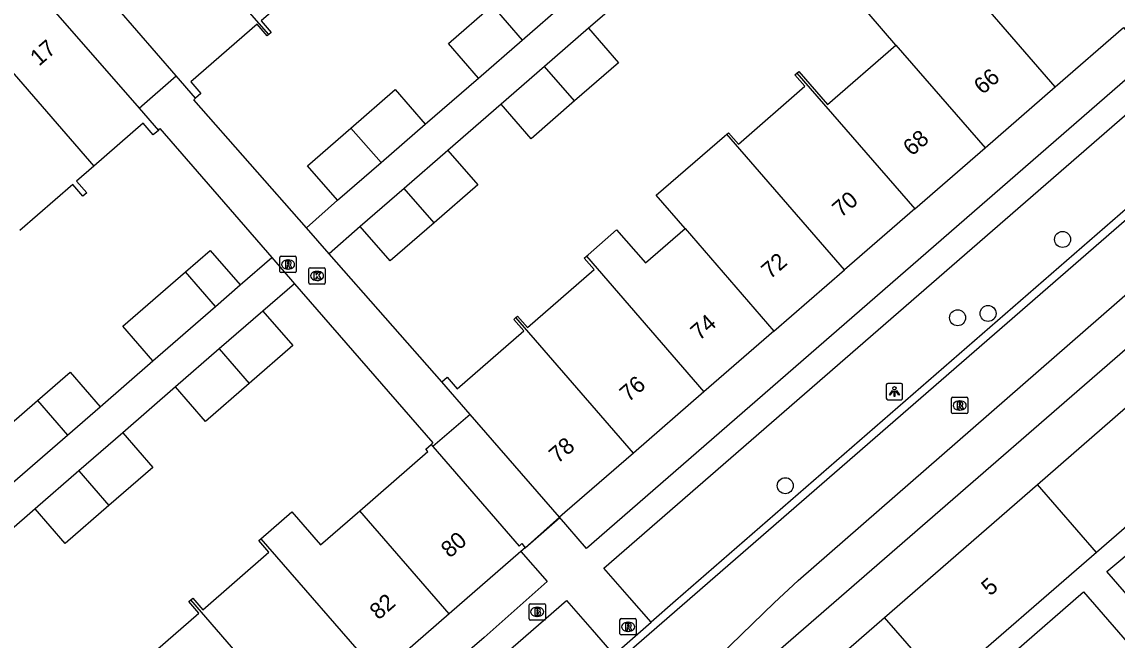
# Model space of a CAD drawing. Extents: x 155888 to 156864, y 383882 to 384671.
# Drawn here: x 156546.3 to 156613.4, y 384111.8 to 384149.6 of the extents above; entities that cross this region are included whole.
import ezdxf

# ---------------------------------------------------------------- set-up
doc = ezdxf.new("R2010")
doc.units = 0
for name, color, linetype in [('IMGEO_Boom', 7, 'Continuous'), ('IMGEO_Brandkraan', 7, 'Continuous'), ('IMGEO_Kolk', 7, 'Continuous'), ('IMGEO_Lichtpunt', 7, 'Continuous'), ('IMGEO_Pand', 7, 'Continuous'), ('IMGEO_Pand_nummerreeks', 7, 'Continuous'), ('IMGEO_Pand_overbouw', 7, 'Continuous'), ('IMGEO_Rijbaan_lokaal_gesloten', 7, 'Continuous'), ('IMGEO_Rijbaan_lokaal_open', 7, 'Continuous'), ('IMGEO_Rioolput', 7, 'Continuous'), ('IMGEO_Voetpad_open', 7, 'Continuous')]:
    doc.layers.add(name, color=color, linetype=linetype)

msp = doc.modelspace()

# ---------------------------------------------------------------- linework, layer by layer
at = {"layer": 'IMGEO_Boom'}
for centre in [(156610.032, 384136.289), (156605.468, 384131.757), (156603.606, 384131.497), (156593.057, 384121.22)]:
    msp.add_circle(centre, 0.489, dxfattribs=at)
at = {"layer": 'IMGEO_Brandkraan'}
for p, q in [((156577.369, 384113.075), (156577.369, 384113.927)), ((156577.444, 384114.001), (156578.296, 384114.001)), ((156577.857, 384113.781), (156577.882, 384113.781)), ((156578.37, 384113.927), (156578.37, 384113.075)), ((156578.296, 384113.001), (156577.444, 384113.001)), ((156577.88, 384113.221), (156577.855, 384113.221))]:
    msp.add_line(p, q, dxfattribs=at)
for points in [[(156577.369, 384113.075), (156577.369, 384113.927)], [(156577.444, 384114.001), (156578.296, 384114.001)], [(156577.717, 384113.701), (156577.717, 384113.301), (156577.93, 384113.301)], [(156577.948, 384113.701), (156577.717, 384113.701)], [(156577.896, 384113.62), (156577.842, 384113.62), (156577.842, 384113.544)], [(156577.842, 384113.544), (156577.895, 384113.544)], [(156577.904, 384113.468), (156577.842, 384113.468), (156577.842, 384113.387)], [(156578.37, 384113.927), (156578.37, 384113.075)], [(156578.296, 384113.001), (156577.444, 384113.001)], [(156577.842, 384113.387), (156577.904, 384113.387)]]:
    msp.add_lwpolyline(points, dxfattribs=at)
for centre, radius, start, end in [((156577.446, 384113.925), 0.0765, 91.55205, 178.44795), ((156577.446, 384113.925), 0.0765, 91.55205, 178.44795), ((156577.897, 384113.582), 0.0379, 267.82845, 90.93552), ((156577.905, 384113.427), 0.0404, 269.87594, 90.50774), ((156577.952, 384113.556), 0.145, 59.4692, 91.53667), ((156577.977, 384113.603), 0.0922, 285.51372, 58.15012), ((156577.982, 384113.411), 0.105, 301.31148, 78.98903), ((156578.294, 384113.925), 0.0765, 1.55205, 88.44795), ((156578.294, 384113.925), 0.0765, 1.55205, 88.44795), ((156577.446, 384113.077), 0.0765, 181.55205, 268.44795), ((156577.446, 384113.077), 0.0765, 181.55205, 268.44795), ((156577.936, 384113.552), 0.251, 268.66757, 293.53466), ((156578.294, 384113.077), 0.0765, 271.55205, 358.44795), ((156578.294, 384113.077), 0.0765, 271.55205, 358.44795)]:
    msp.add_arc(centre, radius, start, end, dxfattribs=at)
for centre, major_axis, ratio, start_param, end_param in [((156577.856, 384113.501), (-0.387, 0.002), 0.722429, 4.712389, 7.853982), ((156577.881, 384113.501), (-0.39, 0.002), 0.717154, 1.570796, 4.712389)]:
    msp.add_ellipse(centre, major_axis=major_axis, ratio=ratio, start_param=start_param, end_param=end_param, dxfattribs=at)
at = {"layer": 'IMGEO_Kolk'}
for p, q in [((156563.894, 384133.628), (156563.894, 384134.48)), ((156563.969, 384134.554), (156564.821, 384134.554)), ((156564.382, 384134.334), (156564.407, 384134.334)), ((156564.895, 384134.48), (156564.895, 384133.628)), ((156564.821, 384133.554), (156563.969, 384133.554)), ((156564.405, 384133.774), (156564.38, 384133.774))]:
    msp.add_line(p, q, dxfattribs=at)
for points in [[(156563.894, 384133.628), (156563.894, 384134.48)], [(156563.969, 384134.554), (156564.821, 384134.554)], [(156564.215, 384134.254), (156564.338, 384134.254), (156564.338, 384134.103), (156564.468, 384134.254), (156564.632, 384134.254), (156564.486, 384134.103), (156564.639, 384133.854), (156564.487, 384133.854), (156564.402, 384134.018), (156564.338, 384133.951), (156564.338, 384133.854), (156564.215, 384133.854), (156564.215, 384134.254)], [(156564.895, 384134.48), (156564.895, 384133.628)], [(156564.821, 384133.554), (156563.969, 384133.554)]]:
    msp.add_lwpolyline(points, dxfattribs=at)
for centre, start, end in [((156563.971, 384134.478), 91.55205, 178.44795), ((156563.971, 384134.478), 91.55205, 178.44795), ((156564.819, 384134.478), 1.55205, 88.44795), ((156564.819, 384134.478), 1.55205, 88.44795), ((156563.971, 384133.63), 181.55205, 268.44795), ((156563.971, 384133.63), 181.55205, 268.44795), ((156564.819, 384133.63), 271.55205, 358.44795), ((156564.819, 384133.63), 271.55205, 358.44795)]:
    msp.add_arc(centre, 0.0765, start, end, dxfattribs=at)
for centre, major_axis, ratio, start_param, end_param in [((156564.381, 384134.054), (-0.387, 0.002), 0.722429, 4.712389, 7.853982), ((156564.406, 384134.054), (-0.39, 0.002), 0.717154, 1.570796, 4.712389)]:
    msp.add_ellipse(centre, major_axis=major_axis, ratio=ratio, start_param=start_param, end_param=end_param, dxfattribs=at)
at = {"layer": 'IMGEO_Lichtpunt'}
for p, q in [((156599.24, 384127.384), (156599.24, 384126.577)), ((156599.24, 384127.384), (156599.24, 384126.577)), ((156600.142, 384127.479), (156599.334, 384127.479)), ((156600.142, 384127.479), (156599.334, 384127.479)), ((156600.236, 384126.577), (156600.236, 384127.384)), ((156600.236, 384126.577), (156600.236, 384127.384)), ((156599.334, 384126.483), (156600.142, 384126.483)), ((156599.334, 384126.483), (156600.142, 384126.483))]:
    msp.add_line(p, q, dxfattribs=at)
for points in [[(156599.614, 384127.048), (156599.653, 384127.02), (156599.465, 384126.758), (156599.427, 384126.785), (156599.614, 384127.048)], [(156599.716, 384127), (156599.763, 384127), (156599.763, 384126.678), (156599.716, 384126.678), (156599.716, 384127)], [(156599.826, 384127.02), (156599.864, 384127.047), (156600.051, 384126.785), (156600.012, 384126.757), (156599.826, 384127.02)]]:
    msp.add_lwpolyline(points, dxfattribs=at)
msp.add_circle((156599.739, 384127.182), 0.0994, dxfattribs=at)
for centre, start, end in [((156599.334, 384127.384), 90, 180), ((156599.334, 384127.384), 90, 180), ((156600.142, 384127.384), 0, 90), ((156600.142, 384127.384), 0, 90), ((156599.334, 384126.577), 180, 270), ((156599.334, 384126.577), 180, 270), ((156600.142, 384126.577), 270, 0), ((156600.142, 384126.577), 270, 360)]:
    msp.add_arc(centre, 0.0946, start, end, dxfattribs=at)
at = {"layer": 'IMGEO_Pand'}
for points in [[(156561.441, 384148.826), (156554.174, 384157.103)], [(156599.829, 384148.182), (156598.187, 384150.072), (156596.034, 384152.551), (156600.336, 384156.287), (156602.489, 384153.808)], [(156609.582, 384145.625), (156604.264, 384151.76), (156604.127, 384151.918), (156602.489, 384153.808)], [(156556.961, 384144.933), (156555.775, 384146.301), (156549.746, 384153.257)], [(156565.766, 384152.585), (156565.653, 384152.487), (156565.036, 384153.196), (156560.967, 384149.66), (156561.583, 384148.95), (156561.441, 384148.826)], [(156547.618, 384151.401), (156547.827, 384151.16), (156547.661, 384151.015), (156553.498, 384144.317), (156554.683, 384142.957)], [(156574.273, 384146.161), (156572.441, 384148.273), (156575.112, 384150.59)], [(156575.112, 384150.59), (156576.951, 384148.484)], [(156576.951, 384148.484), (156579.629, 384150.807)], [(156561.441, 384148.826), (156561.349, 384148.746), (156560.732, 384149.455), (156556.663, 384145.919), (156557.279, 384145.209), (156556.961, 384144.933)], [(156581.015, 384149.21), (156578.326, 384146.876)], [(156581.015, 384149.21), (156582.848, 384147.098), (156580.157, 384144.763)], [(156609.582, 384145.625), (156613.768, 384149.257), (156615.216, 384147.588), (156615.406, 384147.37)], [(156544.113, 384148.367), (156550.722, 384140.76)], [(156574.273, 384146.161), (156576.951, 384148.484)], [(156593.768, 384146.462), (156593.879, 384146.559), (156595.637, 384144.538), (156599.829, 384148.182)], [(156599.829, 384148.182), (156605.287, 384141.898)], [(156578.326, 384146.876), (156575.66, 384144.563)], [(156580.157, 384144.763), (156578.326, 384146.876)], [(156589.471, 384142.727), (156589.576, 384142.818), (156590.187, 384142.118), (156594.254, 384145.654), (156593.645, 384146.356), (156593.768, 384146.462)], [(156593.768, 384146.462), (156600.977, 384138.159)], [(156605.287, 384141.898), (156609.582, 384145.625)], [(156566.47, 384143.098), (156569.183, 384145.452), (156571.018, 384143.337)], [(156580.157, 384144.763), (156577.493, 384142.451), (156575.66, 384144.563)], [(156554.683, 384142.957), (156554.366, 384142.681), (156553.749, 384143.391), (156550.722, 384140.76)], [(156565.654, 384138.684), (156563.819, 384140.799), (156566.47, 384143.098)], [(156566.47, 384143.098), (156568.317, 384140.994)], [(156568.317, 384140.994), (156571.018, 384143.337)], [(156586.92, 384136.96), (156585.16, 384138.991), (156589.341, 384142.614), (156589.471, 384142.727)], [(156596.673, 384134.424), (156589.471, 384142.727)], [(156572.405, 384141.737), (156569.725, 384139.411)], [(156572.405, 384141.737), (156574.24, 384139.622), (156571.558, 384137.295)], [(156600.977, 384138.159), (156605.287, 384141.898)], [(156565.654, 384138.684), (156568.317, 384140.994)], [(156550.722, 384140.76), (156549.679, 384139.853), (156550.296, 384139.143), (156550.061, 384138.938), (156549.444, 384139.648), (156546.193, 384136.824)], [(156569.725, 384139.411), (156567.043, 384137.084)], [(156571.558, 384137.295), (156569.725, 384139.411)], [(156600.977, 384138.159), (156596.673, 384134.424)], [(156571.558, 384137.295), (156568.878, 384134.969), (156567.043, 384137.084)], [(156580.881, 384135.259), (156580.98, 384135.345), (156582.732, 384136.869), (156584.491, 384134.848), (156586.92, 384136.96)], [(156586.92, 384136.96), (156592.361, 384130.682)], [(156556.337, 384134.297), (156557.857, 384135.617), (156559.69, 384133.506)], [(156576.571, 384131.512), (156576.67, 384131.598), (156577.28, 384130.897), (156581.355, 384134.439), (156580.745, 384135.141), (156580.881, 384135.259)], [(156580.881, 384135.259), (156588.075, 384126.964)], [(156554.338, 384128.859), (156552.505, 384130.97), (156556.337, 384134.297)], [(156558.171, 384132.187), (156556.337, 384134.297)], [(156592.361, 384130.682), (156596.673, 384134.424)], [(156558.171, 384132.187), (156559.69, 384133.506)], [(156554.338, 384128.859), (156558.171, 384132.187)], [(156561.079, 384131.906), (156558.407, 384129.585)], [(156561.079, 384131.906), (156562.912, 384129.795), (156560.24, 384127.475)], [(156572.041, 384127.575), (156572.359, 384127.851), (156572.969, 384127.15), (156577.044, 384130.692), (156576.434, 384131.394), (156576.571, 384131.512)], [(156583.759, 384123.219), (156576.571, 384131.512)], [(156592.361, 384130.682), (156588.075, 384126.964)], [(156558.407, 384129.585), (156555.727, 384127.258)], [(156558.407, 384129.585), (156560.24, 384127.475)], [(156608.489, 384121.292), (156617.846, 384129.421)], [(156547.274, 384126.431), (156549.273, 384128.167), (156551.108, 384126.054)], [(156579.234, 384119.292), (156573.771, 384125.581), (156572.041, 384127.575)], [(156560.24, 384127.475), (156557.56, 384125.147), (156555.727, 384127.258)], [(156588.075, 384126.964), (156583.759, 384123.219)], [(156545.749, 384121.4), (156543.914, 384123.513), (156547.274, 384126.431)], [(156547.274, 384126.431), (156549.109, 384124.318)], [(156549.109, 384124.318), (156551.108, 384126.054)], [(156621.464, 384125.256), (156612.102, 384117.132)], [(156545.749, 384121.4), (156549.109, 384124.318)], [(156552.497, 384124.453), (156549.818, 384122.126)], [(156552.497, 384124.453), (156554.332, 384122.34), (156551.651, 384120.012)], [(156567.005, 384119.687), (156571.185, 384123.318), (156571.048, 384123.457), (156571.374, 384123.74)], [(156571.374, 384123.74), (156571.489, 384123.608), (156576.761, 384117.53), (156576.924, 384117.676), (156577.132, 384117.425)], [(156583.759, 384123.219), (156579.569, 384119.583), (156579.234, 384119.292)], [(156549.818, 384122.126), (156547.138, 384119.799)], [(156549.818, 384122.126), (156551.651, 384120.012)], [(156599.132, 384113.164), (156608.489, 384121.292)], [(156612.102, 384117.132), (156608.489, 384121.292)], [(156551.651, 384120.012), (156548.973, 384117.686), (156547.138, 384119.799)], [(156560.961, 384117.973), (156562.856, 384119.628), (156564.613, 384117.608), (156567.005, 384119.687)], [(156572.48, 384113.384), (156567.005, 384119.687)], [(156556.662, 384114.234), (156556.785, 384114.341), (156557.402, 384113.632), (156561.451, 384117.156), (156560.835, 384117.863), (156560.961, 384117.973)], [(156560.961, 384117.973), (156568.188, 384109.654)], [(156576.865, 384117.193), (156572.48, 384113.384)], [(156577.132, 384117.425), (156576.865, 384117.193)], [(156612.102, 384117.132), (156602.741, 384109.01)], [(156552.36, 384110.49), (156552.468, 384110.584), (156553.085, 384109.875), (156557.154, 384113.416), (156556.537, 384114.125), (156556.662, 384114.234)], [(156563.88, 384105.911), (156556.662, 384114.234)], [(156572.48, 384113.384), (156568.188, 384109.654)], [(156593.133, 384100.673), (156589.53, 384104.822), (156599.132, 384113.164)], [(156602.741, 384109.01), (156599.132, 384113.164)]]:
    msp.add_lwpolyline(points, dxfattribs=at)
at = {"layer": 'IMGEO_Pand_overbouw'}
for points in [[(156553.498, 384144.317), (156555.775, 384146.301), (156549.746, 384153.257), (156547.618, 384151.401), (156547.827, 384151.16), (156547.661, 384151.015)], [(156577.132, 384117.425), (156579.256, 384119.267), (156579.234, 384119.292), (156573.771, 384125.581), (156571.489, 384123.608), (156576.761, 384117.53), (156576.924, 384117.676)]]:
    msp.add_lwpolyline(points, close=True, dxfattribs=at)
at = {"layer": 'IMGEO_Rijbaan_lokaal_gesloten'}
for points in [[(156528.389, 384063.906), (156532.781, 384067.236), (156536.903, 384070.55), (156552.177, 384083.855), (156568.729, 384098.213), (156583.48, 384111.077), (156616.441, 384139.692), (156618.873, 384141.904), (156620.066, 384143.035), (156621.243, 384144.182), (156623.55, 384146.525), (156624.152, 384147.224), (156624.451, 384147.625)], [(156583.599, 384105.173), (156584.982, 384106.904), (156592.374, 384114.06), (156593.839, 384115.427), (156617.343, 384135.911), (156620.351, 384138.467), (156622.416, 384140.04), (156625.179, 384141.829)]]:
    msp.add_lwpolyline(points, dxfattribs=at)
at = {"layer": 'IMGEO_Rijbaan_lokaal_open'}
for points in [[(156619.562, 384143.22), (156615.912, 384139.864), (156586.343, 384114.171), (156584.84, 384112.864)], [(156582.557, 384110.877), (156584.84, 384112.864)]]:
    msp.add_lwpolyline(points, dxfattribs=at)
at = {"layer": 'IMGEO_Rioolput'}
for p, q in [((156562.121, 384134.328), (156562.121, 384135.18)), ((156562.196, 384135.254), (156563.048, 384135.254)), ((156562.609, 384135.034), (156562.634, 384135.034)), ((156563.122, 384135.18), (156563.122, 384134.328)), ((156563.048, 384134.254), (156562.196, 384134.254)), ((156562.632, 384134.474), (156562.607, 384134.474)), ((156603.231, 384125.703), (156603.231, 384126.555)), ((156603.306, 384126.629), (156604.158, 384126.629)), ((156603.719, 384126.409), (156603.744, 384126.409)), ((156604.232, 384126.555), (156604.232, 384125.703)), ((156604.158, 384125.629), (156603.306, 384125.629)), ((156603.742, 384125.849), (156603.717, 384125.849)), ((156582.937, 384112.16), (156582.937, 384113.012)), ((156583.012, 384113.086), (156583.864, 384113.086)), ((156583.425, 384112.866), (156583.45, 384112.866)), ((156583.938, 384113.012), (156583.938, 384112.16)), ((156583.864, 384112.086), (156583.012, 384112.086)), ((156583.448, 384112.306), (156583.423, 384112.306))]:
    msp.add_line(p, q, dxfattribs=at)
for points in [[(156562.121, 384134.328), (156562.121, 384135.18)], [(156562.196, 384135.254), (156563.048, 384135.254)], [(156562.71, 384134.952), (156562.458, 384134.954), (156562.458, 384134.554)], [(156563.122, 384135.18), (156563.122, 384134.328)], [(156563.048, 384134.254), (156562.196, 384134.254)], [(156562.458, 384134.554), (156562.582, 384134.554), (156562.582, 384134.716), (156562.593, 384134.716)], [(156562.636, 384134.873), (156562.582, 384134.873), (156562.582, 384134.792)], [(156562.582, 384134.792), (156562.634, 384134.792)], [(156562.64, 384134.687), (156562.711, 384134.554), (156562.851, 384134.554), (156562.786, 384134.68)], [(156603.231, 384125.703), (156603.231, 384126.555)], [(156603.306, 384126.629), (156604.158, 384126.629)], [(156603.82, 384126.327), (156603.568, 384126.329), (156603.568, 384125.929)], [(156603.746, 384126.248), (156603.692, 384126.248), (156603.692, 384126.167)], [(156603.692, 384126.167), (156603.744, 384126.167)], [(156604.232, 384126.555), (156604.232, 384125.703)], [(156604.158, 384125.629), (156603.306, 384125.629)], [(156603.568, 384125.929), (156603.692, 384125.929), (156603.692, 384126.091), (156603.703, 384126.091)], [(156603.75, 384126.062), (156603.821, 384125.929), (156603.961, 384125.929), (156603.896, 384126.055)], [(156582.937, 384112.16), (156582.937, 384113.012)], [(156583.012, 384113.086), (156583.864, 384113.086)], [(156583.526, 384112.784), (156583.274, 384112.786), (156583.274, 384112.386)], [(156583.938, 384113.012), (156583.938, 384112.16)], [(156583.864, 384112.086), (156583.012, 384112.086)], [(156583.274, 384112.386), (156583.398, 384112.386), (156583.398, 384112.548), (156583.409, 384112.548)], [(156583.452, 384112.705), (156583.398, 384112.705), (156583.398, 384112.624)], [(156583.398, 384112.624), (156583.45, 384112.624)], [(156583.456, 384112.519), (156583.527, 384112.386), (156583.667, 384112.386), (156583.602, 384112.512)]]:
    msp.add_lwpolyline(points, dxfattribs=at)
for centre, radius, start, end in [((156562.198, 384135.178), 0.0765, 91.55205, 178.44795), ((156562.198, 384135.178), 0.0765, 91.55205, 178.44795), ((156562.709, 384134.842), 0.109, 350.36119, 89.41601), ((156563.046, 384135.178), 0.0765, 1.55205, 88.44795), ((156563.046, 384135.178), 0.0765, 1.55205, 88.44795), ((156562.198, 384134.33), 0.0765, 181.55205, 268.44795), ((156562.198, 384134.33), 0.0765, 181.55205, 268.44795), ((156562.592, 384134.663), 0.0533, 26.02933, 88.69889), ((156562.618, 384134.981), 0.19, 274.7715, 282.96867), ((156562.642, 384134.777), 0.0964, 77.00612, 93.18647), ((156562.656, 384134.834), 0.0378, 276.66336, 79.67722), ((156562.707, 384134.842), 0.112, 277.58423, 350.98172), ((156562.691, 384134.627), 0.108, 29.51342, 73.79051), ((156563.046, 384134.33), 0.0765, 271.55205, 358.44795), ((156563.046, 384134.33), 0.0765, 271.55205, 358.44795), ((156603.308, 384126.553), 0.0765, 91.55205, 178.44795), ((156603.308, 384126.553), 0.0765, 91.55205, 178.44795), ((156603.728, 384126.356), 0.19, 274.7715, 282.96867), ((156603.752, 384126.152), 0.0964, 77.00612, 93.18647), ((156603.766, 384126.209), 0.0378, 276.66336, 79.67722), ((156603.819, 384126.217), 0.109, 350.36119, 89.41601), ((156603.817, 384126.217), 0.112, 277.58423, 350.98172), ((156604.156, 384126.553), 0.0765, 1.55205, 88.44795), ((156604.156, 384126.553), 0.0765, 1.55205, 88.44795), ((156603.308, 384125.705), 0.0765, 181.55205, 268.44795), ((156603.308, 384125.705), 0.0765, 181.55205, 268.44795), ((156603.702, 384126.038), 0.0533, 26.02933, 88.69889), ((156603.801, 384126.002), 0.108, 29.51342, 73.79051), ((156604.156, 384125.705), 0.0765, 271.55205, 358.44795), ((156604.156, 384125.705), 0.0765, 271.55205, 358.44795), ((156583.014, 384113.01), 0.0765, 91.55205, 178.44795), ((156583.014, 384113.01), 0.0765, 91.55205, 178.44795), ((156583.525, 384112.674), 0.109, 350.36119, 89.41601), ((156583.862, 384113.01), 0.0765, 1.55205, 88.44795), ((156583.862, 384113.01), 0.0765, 1.55205, 88.44795), ((156583.014, 384112.162), 0.0765, 181.55205, 268.44795), ((156583.014, 384112.162), 0.0765, 181.55205, 268.44795), ((156583.408, 384112.495), 0.0533, 26.02933, 88.69889), ((156583.434, 384112.813), 0.19, 274.7715, 282.96867), ((156583.458, 384112.609), 0.0964, 77.00612, 93.18647), ((156583.472, 384112.666), 0.0378, 276.66336, 79.67722), ((156583.523, 384112.674), 0.112, 277.58423, 350.98172), ((156583.507, 384112.459), 0.108, 29.51342, 73.79051), ((156583.862, 384112.162), 0.0765, 271.55205, 358.44795), ((156583.862, 384112.162), 0.0765, 271.55205, 358.44795)]:
    msp.add_arc(centre, radius, start, end, dxfattribs=at)
for centre, major_axis, ratio, start_param, end_param in [((156562.608, 384134.754), (-0.387, 0.002), 0.722429, 4.712389, 7.853982), ((156562.633, 384134.754), (-0.39, 0.002), 0.717154, 1.570796, 4.712389), ((156603.718, 384126.129), (-0.387, 0.002), 0.722429, 4.712389, 7.853982), ((156603.743, 384126.129), (-0.39, 0.002), 0.717154, 1.570796, 4.712389), ((156583.424, 384112.586), (-0.387, 0.002), 0.722429, 4.712389, 7.853982), ((156583.449, 384112.586), (-0.39, 0.002), 0.717154, 1.570796, 4.712389)]:
    msp.add_ellipse(centre, major_axis=major_axis, ratio=ratio, start_param=start_param, end_param=end_param, dxfattribs=at)
at = {"layer": 'IMGEO_Voetpad_open'}
for points in [[(156584.247, 384152.015), (156581.015, 384149.21)], [(156615.406, 384147.37), (156580.896, 384117.376), (156579.234, 384119.292)], [(156584.84, 384112.864), (156583.519, 384114.376), (156581.95, 384116.172), (156616.774, 384146.419)], [(156571.018, 384143.337), (156574.273, 384146.161)], [(156563.743, 384137.002), (156556.855, 384144.826), (156556.961, 384144.933)], [(156575.66, 384144.563), (156572.405, 384141.737)], [(156554.683, 384142.957), (156554.762, 384143.072), (156561.617, 384135.18)], [(156587.667, 384106.816), (156626.242, 384140.297)], [(156563.743, 384137.002), (156565.654, 384138.684)], [(156565.143, 384135.411), (156563.743, 384137.002)], [(156567.043, 384137.084), (156565.143, 384135.411)], [(156559.69, 384133.506), (156561.617, 384135.18)], [(156561.617, 384135.18), (156563.019, 384133.568)], [(156572.041, 384127.575), (156565.143, 384135.411)], [(156563.019, 384133.568), (156561.079, 384131.906)], [(156563.019, 384133.568), (156571.475, 384123.833), (156571.374, 384123.74)], [(156551.108, 384126.054), (156554.338, 384128.859)], [(156555.727, 384127.258), (156552.497, 384124.453)], [(156644.608, 384079.3), (156612.746, 384115.979), (156624.624, 384125.881)], [(156547.138, 384119.799), (156543.892, 384116.981)], [(156579.234, 384119.292), (156577.132, 384117.425)], [(156576.865, 384117.193), (156578.489, 384115.359), (156574.615, 384111.942), (156571.103, 384108.893), (156570.32, 384108.213), (156566.807, 384105.148), (156566.005, 384104.472), (156562.509, 384101.408), (156561.721, 384100.736), (156558.21, 384097.677), (156557.417, 384096.994), (156553.895, 384093.933), (156553.113, 384093.241), (156549.6, 384090.192), (156548.818, 384089.519), (156548.425, 384089.16), (156548.108, 384088.885), (156546.461, 384090.777)], [(156552.051, 384084.344), (156550.734, 384085.846), (156549.131, 384087.675), (156579.669, 384114.204), (156581.24, 384112.394), (156582.557, 384110.877)], [(156602.78, 384107.311), (156611.304, 384114.726), (156643.166, 384078.047)]]:
    msp.add_lwpolyline(points, dxfattribs=at)

# ---------------------------------------------------------------- texts
at = {"layer": 'IMGEO_Pand_nummerreeks'}
for s, rotation, p in [('17', 40.87744, (156547.373, 384146.85)), ('66', 40.94929, (156605.138, 384145.106)), ('68', 40.94773, (156600.805, 384141.346)), ('70', 40.94773, (156596.47, 384137.585)), ('72', 40.94773, (156592.129, 384133.819)), ('74', 40.94773, (156587.797, 384130.059)), ('76', 40.94773, (156583.461, 384126.297)), ('78', 40.94773, (156579.128, 384122.538)), ('80', 40.98538, (156572.518, 384116.756)), ('5', 40.98162, (156605.597, 384114.435)), ('82', 40.98538, (156568.155, 384112.965))]:
    msp.add_text(s, height=1, rotation=rotation, dxfattribs=at).set_placement(p)

doc.saveas('drawing.dxf')
